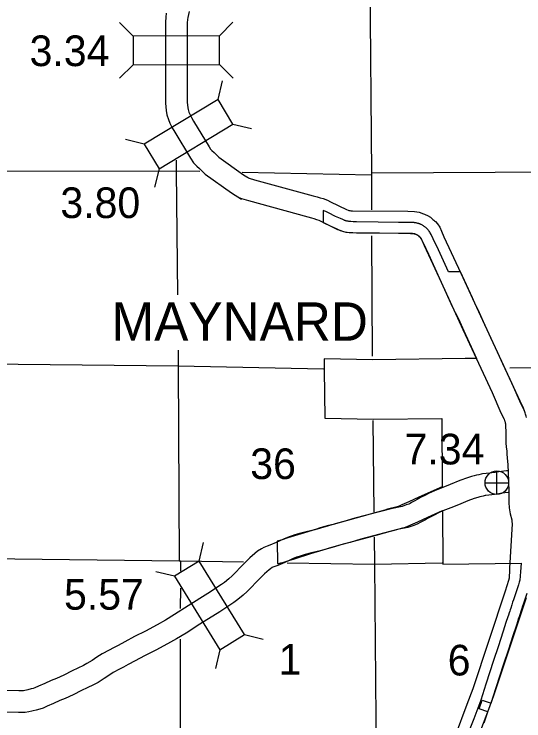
# Model space of a CAD drawing. Extents: x 1369885 to 1370219, y 379980 to 380218.
# Drawn here: x 1369916.19 to 1369938.61, y 380148.46 to 380179.57 of the extents above; entities that cross this region are included whole.
import ezdxf

# ---------------------------------------------------------------- set-up
doc = ezdxf.new("R2010")
doc.units = 0
for name, color, linetype in [('Level 10', 7, 'Continuous'), ('Level 20', 7, 'Continuous'), ('Level 25', 7, 'Continuous'), ('Level 26', 7, 'Continuous'), ('Level 4', 7, 'Continuous'), ('Level 5', 7, 'Continuous'), ('Level 58', 7, 'Continuous'), ('Level 6', 7, 'Continuous')]:
    doc.layers.add(name, color=color, linetype=linetype)

msp = doc.modelspace()

# ---------------------------------------------------------------- linework, layer by layer
at = {"layer": 'Level 10'}
for points in [[(1369923.887, 380179.675), (1369923.854, 380179.553), (1369923.824, 380179.422), (1369923.809, 380179.331), (1369923.799, 380179.18), (1369923.806, 380175.686), (1369923.826, 380175.447), (1369923.84, 380175.369), (1369923.88, 380175.25), (1369923.915, 380175.157), (1369923.989, 380175.017), (1369924.081, 380174.851), (1369924.762, 380173.726), (1369924.831, 380173.616), (1369924.882, 380173.564), (1369924.99, 380173.469), (1369925.14, 380173.322), (1369925.192, 380173.276), (1369926.282, 380172.499), (1369926.424, 380172.41), (1369926.449, 380172.386), (1369926.492, 380172.36)], [(1369922.883, 380179.605), (1369922.856, 380179.438), (1369922.841, 380179.21), (1369922.848, 380175.645), (1369922.875, 380175.322), (1369922.909, 380175.131), (1369922.977, 380174.927), (1369923.041, 380174.762), (1369923.146, 380174.562), (1369923.252, 380174.37), (1369923.946, 380173.223), (1369924.074, 380173.02), (1369924.222, 380172.868), (1369924.339, 380172.765), (1369924.486, 380172.622), (1369924.593, 380172.526), (1369925.747, 380171.704), (1369926.196, 380171.419)], [(1369926.438, 380172.388), (1369926.532, 380172.346), (1369926.759, 380172.276), (1369929.338, 380171.567), (1369929.523, 380171.523), (1369929.656, 380171.482), (1369929.78, 380171.445), (1369929.974, 380171.377), (1369930.105, 380171.308), (1369930.811, 380170.968), (1369930.879, 380170.94), (1369930.915, 380170.925), (1369930.955, 380170.916), (1369930.994, 380170.911), (1369931.066, 380170.911), (1369933.503, 380170.887), (1369933.803, 380170.873), (1369934.01, 380170.846), (1369934.189, 380170.782), (1369934.239, 380170.755), (1369934.263, 380170.745), (1369934.365, 380170.7), (1369934.498, 380170.629), (1369934.552, 380170.579), (1369934.611, 380170.533), (1369934.65, 380170.497), (1369934.681, 380170.468), (1369934.722, 380170.435), (1369934.812, 380170.336), (1369934.911, 380170.185), (1369934.992, 380170.02), (1369935.096, 380169.771), (1369935.836, 380168.168), (1369936.797, 380166.091), (1369938.088, 380163.302), (1369938.473, 380162.421), (1369938.607, 380162.151), (1369938.643, 380162.069)], [(1369926.049, 380171.512), (1369926.196, 380171.447), (1369926.492, 380171.356), (1369929.101, 380170.638), (1369929.27, 380170.598), (1369929.377, 380170.565), (1369929.485, 380170.533), (1369929.589, 380170.497), (1369929.673, 380170.452), (1369930.417, 380170.094), (1369930.518, 380170.052), (1369930.631, 380170.007), (1369930.784, 380169.972), (1369930.931, 380169.952), (1369931.064, 380169.953), (1369933.476, 380169.929), (1369933.719, 380169.918), (1369933.783, 380169.909), (1369933.798, 380169.904), (1369933.826, 380169.889), (1369933.886, 380169.864), (1369933.943, 380169.839), (1369933.989, 380169.803), (1369933.996, 380169.796), (1369934.051, 380169.745), (1369934.056, 380169.741), (1369934.076, 380169.71), (1369934.119, 380169.623), (1369934.218, 380169.385), (1369934.966, 380167.766), (1369935.928, 380165.688), (1369937.214, 380162.909), (1369937.604, 380162.016), (1369937.739, 380161.744), (1369937.745, 380161.732), (1369937.76, 380161.682), (1369937.78, 380161.644), (1369937.791, 380161.578), (1369937.799, 380161.532), (1369937.806, 380161.41), (1369937.814, 380161.196), (1369937.814, 380160.93), (1369937.824, 380160.683), (1369937.837, 380160.521), (1369937.857, 380160.328), (1369937.868, 380160.201), (1369937.88, 380160.031), (1369937.889, 380159.879), (1369937.9, 380159.745), (1369937.931, 380159.007), (1369937.942, 380158.54), (1369937.942, 380158.284), (1369937.95, 380158.066), (1369937.962, 380157.835), (1369938.007, 380157.576), (1369938.078, 380157.311), (1369938.086, 380157.23), (1369938.09, 380157.135), (1369937.979, 380155.177), (1369937.974, 380154.973), (1369937.966, 380154.88), (1369937.957, 380154.741), (1369937.928, 380154.638), (1369937.793, 380154.164), (1369936.366, 380149.875), (1369936.108, 380149.178), (1369935.591, 380147.802)], [(1369937.902, 380159.464), (1369937.84, 380159.459), (1369937.514, 380159.427), (1369937.342, 380159.395), (1369937.206, 380159.372), (1369937.116, 380159.367), (1369936.796, 380159.327), (1369936.726, 380159.315), (1369936.627, 380159.295), (1369936.526, 380159.274), (1369936.417, 380159.245), (1369936.312, 380159.215), (1369936.127, 380159.159), (1369935.799, 380159.04), (1369935.371, 380158.859), (1369935.042, 380158.727), (1369934.684, 380158.586), (1369934.449, 380158.485), (1369934.251, 380158.386), (1369934.068, 380158.289), (1369933.92, 380158.209), (1369933.809, 380158.148), (1369933.671, 380158.069), (1369933.603, 380158.031), (1369933.55, 380158.004), (1369933.44, 380157.963), (1369933.25, 380157.895), (1369932.838, 380157.811), (1369931.182, 380157.382), (1369930.698, 380157.235), (1369930.411, 380157.155), (1369930.02, 380157.046), (1369929.411, 380156.875), (1369929.038, 380156.784), (1369928.735, 380156.707), (1369928.531, 380156.644), (1369928.425, 380156.611), (1369928.284, 380156.563), (1369928.067, 380156.479), (1369927.88, 380156.384), (1369927.711, 380156.309), (1369927.435, 380156.191), (1369927.323, 380156.151), (1369927.179, 380156.095), (1369927.063, 380156.036), (1369926.891, 380155.924), (1369926.776, 380155.825), (1369926.56, 380155.632), (1369926.364, 380155.446), (1369926.125, 380155.21), (1369925.948, 380155.012), (1369925.776, 380154.849), (1369925.626, 380154.708), (1369925.446, 380154.557), (1369925.305, 380154.457), (1369924.711, 380154.059), (1369923.851, 380153.528), (1369923.24, 380153.137), (1369922.846, 380152.891), (1369922.481, 380152.691), (1369921.971, 380152.415), (1369921.484, 380152.169), (1369921.058, 380151.941), (1369920.759, 380151.782), (1369920.558, 380151.673), (1369920.374, 380151.579), (1369920.067, 380151.411), (1369919.83, 380151.262), (1369919.619, 380151.121), (1369919.394, 380150.978), (1369919.244, 380150.895), (1369918.985, 380150.773), (1369918.74, 380150.656), (1369918.372, 380150.478), (1369918.051, 380150.327), (1369917.82, 380150.232), (1369917.535, 380150.102), (1369917.258, 380149.981), (1369917.1, 380149.912), (1369917.032, 380149.886), (1369916.933, 380149.863), (1369916.797, 380149.829), (1369916.73, 380149.812), (1369916.657, 380149.793), (1369916.6, 380149.785), (1369916.389, 380149.781), (1369915.778, 380149.797)], [(1369937.928, 380158.505), (1369937.925, 380158.504), (1369937.647, 380158.477), (1369937.509, 380158.452), (1369937.316, 380158.418), (1369937.202, 380158.412), (1369936.938, 380158.379), (1369936.901, 380158.373), (1369936.817, 380158.356), (1369936.747, 380158.342), (1369936.673, 380158.322), (1369936.583, 380158.296), (1369936.43, 380158.249), (1369936.15, 380158.148), (1369935.736, 380157.973), (1369935.396, 380157.836), (1369935.048, 380157.699), (1369934.853, 380157.616), (1369934.69, 380157.534), (1369934.52, 380157.444), (1369934.377, 380157.366), (1369934.277, 380157.312), (1369934.142, 380157.235), (1369934.055, 380157.186), (1369933.94, 380157.127), (1369933.769, 380157.063), (1369933.508, 380156.97), (1369933.055, 380156.877), (1369931.442, 380156.459), (1369930.965, 380156.314), (1369930.667, 380156.232), (1369930.278, 380156.123), (1369929.654, 380155.948), (1369929.271, 380155.855), (1369928.995, 380155.784), (1369928.815, 380155.729), (1369928.721, 380155.699), (1369928.611, 380155.662), (1369928.459, 380155.603), (1369928.292, 380155.518), (1369928.093, 380155.43), (1369927.783, 380155.297), (1369927.657, 380155.253), (1369927.57, 380155.219), (1369927.543, 380155.205), (1369927.468, 380155.156), (1369927.407, 380155.104), (1369927.209, 380154.926), (1369927.03, 380154.757), (1369926.821, 380154.551), (1369926.637, 380154.344), (1369926.433, 380154.151), (1369926.262, 380153.991), (1369926.033, 380153.798), (1369925.849, 380153.668), (1369925.23, 380153.253), (1369924.361, 380152.717), (1369923.752, 380152.327), (1369923.331, 380152.064), (1369922.94, 380151.849), (1369922.415, 380151.565), (1369921.926, 380151.319), (1369921.509, 380151.096), (1369921.212, 380150.938), (1369921.005, 380150.825), (1369920.822, 380150.732), (1369920.552, 380150.584), (1369920.352, 380150.458), (1369920.144, 380150.319), (1369919.882, 380150.152), (1369919.679, 380150.041), (1369919.396, 380149.908), (1369919.156, 380149.792), (1369918.784, 380149.613), (1369918.439, 380149.45), (1369918.202, 380149.353), (1369917.926, 380149.226), (1369917.642, 380149.103), (1369917.463, 380149.025), (1369917.313, 380148.968), (1369917.159, 380148.932), (1369917.03, 380148.899), (1369916.965, 380148.883), (1369916.843, 380148.852), (1369916.678, 380148.828), (1369916.385, 380148.823), (1369915.761, 380148.839)], [(1369938.709, 380153.881), (1369937.27, 380149.557), (1369937.006, 380148.844), (1369936.488, 380147.464)]]:
    msp.add_lwpolyline(points, dxfattribs=at)
at = {"layer": 'Level 20'}
for p, q in [((1369921.424, 380178.603), (1369920.826, 380179.198)), ((1369925.219, 380178.61), (1369925.814, 380179.208)), ((1369921.426, 380177.338), (1369920.831, 380176.74)), ((1369925.221, 380177.345), (1369925.819, 380176.75)), ((1369925.157, 380175.812), (1369925.359, 380176.631)), ((1369925.812, 380174.73), (1369926.631, 380174.528)), ((1369921.911, 380173.847), (1369921.092, 380174.048)), ((1369922.566, 380172.764), (1369922.364, 380171.946)), ((1369924.322, 380155.486), (1369924.517, 380156.307)), ((1369923.246, 380154.822), (1369922.425, 380155.016)), ((1369926.316, 380152.257), (1369927.137, 380152.063)), ((1369925.24, 380151.592), (1369925.046, 380150.772))]:
    msp.add_line(p, q, dxfattribs=at)
for points in [[(1369921.426, 380177.338), (1369925.221, 380177.345), (1369925.219, 380178.61), (1369921.424, 380178.603)], [(1369922.566, 380172.764), (1369925.812, 380174.73), (1369925.157, 380175.812), (1369921.911, 380173.847)], [(1369923.246, 380154.822), (1369925.24, 380151.592), (1369926.316, 380152.257), (1369924.322, 380155.486)]]:
    msp.add_lwpolyline(points, close=True, dxfattribs=at)
at = {"layer": 'Level 26'}
for p, q in [((1369937.42, 380158.422), (1369937.42, 380159.46)), ((1369936.9, 380158.941), (1369937.939, 380158.941))]:
    msp.add_line(p, q, dxfattribs=at)
msp.add_circle((1369937.42, 380158.941), 0.519, dxfattribs=at)
at = {"layer": 'Level 4'}
for points in [[(1369931.814, 380184.515), (1369931.837, 380181.126), (1369931.833, 380181.027), (1369931.902, 380172.561), (1369931.901, 380172.481), (1369931.907, 380170.949)], [(1369931.911, 380169.81), (1369931.932, 380164.509)], [(1369931.961, 380161.681), (1369932.01, 380157.643)], [(1369932.023, 380156.54), (1369932.037, 380155.354), (1369932.115, 380146.851), (1369932.126, 380146.707), (1369932.199, 380139.989)], [(1369926.278, 380155.441), (1369923.502, 380155.488), (1369923.441, 380155.484), (1369914.997, 380155.591), (1369914.93, 380155.597), (1369906.42, 380155.85), (1369906.378, 380155.851), (1369902.311, 380155.872)], [(1369935.013, 380155.396), (1369932.047, 380155.348), (1369928.199, 380155.408)]]:
    msp.add_lwpolyline(points, dxfattribs=at)
at = {"layer": 'Level 5'}
for points in [[(1369923.321, 380173.142), (1369923.318, 380172.66), (1369923.375, 380167.204)], [(1369924.364, 380172.638), (1369923.318, 380172.66), (1369914.846, 380172.646), (1369906.147, 380173.018), (1369902.311, 380173.036)], [(1369948.675, 380172.819), (1369940.069, 380172.615), (1369931.902, 380172.561)], [(1369931.901, 380172.481), (1369926.215, 380172.6)], [(1369923.4, 380164.783), (1369923.407, 380164.071), (1369923.441, 380155.484)], [(1369929.799, 380163.946), (1369923.407, 380164.071), (1369914.944, 380164.166), (1369906.209, 380164.33), (1369902.311, 380164.411)], [(1369944.671, 380164.098), (1369940.216, 380164.013), (1369938, 380163.984)], [(1369923.502, 380155.488), (1369923.501, 380155.046)], [(1369923.5, 380154.299), (1369923.498, 380153.409)], [(1369923.496, 380152.058), (1369923.487, 380146.925), (1369923.615, 380138.382)]]:
    msp.add_lwpolyline(points, dxfattribs=at)
at = {"layer": 'Level 6'}
for points in [[(1369935.295, 380168.222), (1369934.849, 380169.198), (1369934.623, 380169.682), (1369934.531, 380169.871), (1369934.489, 380169.942), (1369934.468, 380169.976), (1369934.446, 380170.008), (1369934.42, 380170.044), (1369934.401, 380170.07), (1369934.372, 380170.105), (1369934.349, 380170.128), (1369934.319, 380170.156), (1369934.299, 380170.173), (1369934.272, 380170.194), (1369934.25, 380170.209), (1369934.228, 380170.224), (1369934.193, 380170.247), (1369934.171, 380170.261), (1369934.149, 380170.273), (1369934.123, 380170.287), (1369934.095, 380170.302), (1369934.08, 380170.308), (1369934.065, 380170.315), (1369934.048, 380170.322), (1369934.031, 380170.329), (1369934.01, 380170.336), (1369933.988, 380170.344), (1369933.968, 380170.35), (1369933.944, 380170.357), (1369933.921, 380170.363), (1369933.897, 380170.37), (1369933.873, 380170.376), (1369933.847, 380170.38), (1369933.82, 380170.384), (1369933.803, 380170.386), (1369933.783, 380170.388), (1369933.719, 380170.393), (1369933.437, 380170.4), (1369933.094, 380170.402), (1369932.202, 380170.413), (1369931.254, 380170.426), (1369931.107, 380170.43), (1369930.996, 380170.436), (1369930.904, 380170.445), (1369930.875, 380170.45), (1369930.851, 380170.455), (1369930.826, 380170.46), (1369930.796, 380170.468), (1369930.771, 380170.475), (1369930.745, 380170.483), (1369930.725, 380170.49), (1369930.7, 380170.499), (1369930.646, 380170.52), (1369930.542, 380170.564), (1369930.328, 380170.666), (1369930.011, 380170.822), (1369929.934, 380170.858), (1369929.897, 380170.875), (1369929.856, 380170.892), (1369929.779, 380170.922), (1369929.782, 380170.401)], [(1369929.782, 380170.401), (1369930.119, 380170.234), (1369930.347, 380170.126), (1369930.467, 380170.076), (1369930.536, 380170.049), (1369930.595, 380170.028), (1369930.672, 380170.005), (1369930.752, 380169.985), (1369930.837, 380169.97), (1369930.959, 380169.958), (1369931.088, 380169.951), (1369931.244, 380169.947), (1369932.196, 380169.934), (1369933.09, 380169.923), (1369933.429, 380169.921), (1369933.628, 380169.916), (1369933.717, 380169.91), (1369933.757, 380169.904), (1369933.783, 380169.901), (1369933.802, 380169.897), (1369933.827, 380169.89), (1369933.843, 380169.886), (1369933.865, 380169.878), (1369933.879, 380169.873), (1369933.902, 380169.862), (1369933.918, 380169.853), (1369933.942, 380169.839), (1369933.961, 380169.827), (1369933.988, 380169.808), (1369933.999, 380169.799), (1369934.027, 380169.769), (1369934.052, 380169.735), (1369934.079, 380169.694), (1369934.108, 380169.645), (1369934.19, 380169.476), (1369934.414, 380168.997), (1369934.904, 380167.925), (1369935.477, 380166.674), (1369935.589, 380166.43), (1369935.729, 380166.148), (1369935.963, 380165.625), (1369936.289, 380164.916), (1369936.522, 380164.409)], [(1369938.725, 380161.817), (1369938.713, 380161.873), (1369938.689, 380161.96), (1369938.67, 380162.024), (1369938.639, 380162.104), (1369938.59, 380162.219), (1369938.447, 380162.528), (1369938.075, 380163.318), (1369937.688, 380164.174), (1369937.46, 380164.662), (1369937.16, 380165.316), (1369936.836, 380166.021), (1369936.596, 380166.557), (1369936.454, 380166.843), (1369936.348, 380167.074), (1369935.82, 380168.227), (1369935.295, 380168.222)], [(1369936.522, 380164.409), (1369936.022, 380164.403), (1369931.963, 380164.357), (1369929.823, 380164.396), (1369929.827, 380163.917), (1369929.851, 380161.777), (1369931.993, 380161.741), (1369934.995, 380161.775), (1369935.022, 380158.754)], [(1369935.022, 380158.754), (1369933.997, 380158.299), (1369933.557, 380158.103), (1369933.244, 380157.963), (1369933.13, 380157.911), (1369933.037, 380157.883), (1369932.611, 380157.771), (1369932.488, 380157.737), (1369931.848, 380157.559), (1369930.22, 380157.11), (1369930.01, 380157.052), (1369929.8, 380156.994), (1369929.601, 380156.937), (1369929.49, 380156.901), (1369928.956, 380156.735), (1369928.232, 380156.51), (1369927.984, 380156.434), (1369927.765, 380156.367)], [(1369927.838, 380155.384), (1369927.916, 380155.409), (1369928.047, 380155.451), (1369928.266, 380155.518), (1369928.515, 380155.595), (1369929.241, 380155.82), (1369929.779, 380155.988), (1369929.88, 380156.02), (1369930.06, 380156.072), (1369930.264, 380156.128), (1369930.473, 380156.186), (1369931.956, 380156.592), (1369932.112, 380156.638), (1369932.743, 380156.814), (1369932.859, 380156.845), (1369933.287, 380156.958), (1369933.354, 380156.976), (1369933.436, 380157.002), (1369933.509, 380157.03), (1369933.632, 380157.088), (1369933.946, 380157.227), (1369934.388, 380157.424), (1369935.031, 380157.712)], [(1369935.031, 380157.712), (1369935.052, 380155.363), (1369938.495, 380155.401), (1369938.468, 380155.025), (1369938.451, 380154.838), (1369938.443, 380154.769), (1369938.436, 380154.71), (1369938.428, 380154.655), (1369938.42, 380154.616), (1369938.409, 380154.57), (1369938.392, 380154.506), (1369938.375, 380154.449), (1369938.301, 380154.228), (1369938.15, 380153.792), (1369938.114, 380153.68), (1369938.079, 380153.561), (1369938.039, 380153.424), (1369938.015, 380153.353), (1369937.995, 380153.288), (1369937.97, 380153.215), (1369937.93, 380153.109), (1369937.905, 380153.036), (1369937.824, 380152.789), (1369937.697, 380152.412), (1369937.481, 380151.725), (1369937.271, 380151.115), (1369936.941, 380150.08), (1369936.712, 380149.377), (1369936.411, 380148.55), (1369936.093, 380147.74)], [(1369927.765, 380156.367), (1369927.775, 380155.385), (1369927.838, 380155.384)], [(1369936.859, 380148.38), (1369937.031, 380148.852), (1369936.645, 380148.992), (1369936.774, 380149.364), (1369937.17, 380149.235), (1369937.397, 380149.933), (1369937.726, 380150.964), (1369937.936, 380151.575), (1369938.152, 380152.263), (1369938.279, 380152.638), (1369938.36, 380152.884), (1369938.381, 380152.947), (1369938.421, 380153.052), (1369938.451, 380153.14), (1369938.496, 380153.282), (1369938.538, 380153.424), (1369938.572, 380153.539), (1369938.579, 380153.559), (1369938.755, 380154.074)]]:
    msp.add_lwpolyline(points, dxfattribs=at)

# ---------------------------------------------------------------- texts
at = {"layer": 'Level 25'}
msp.add_text('7.34', height=1.3493, dxfattribs=at).set_placement((1369933.363, 380159.747))
at = {"layer": 'Level 5'}
for s, height, p in [('MAYNARD', 1.6867, (1369920.471, 380165.193)), ('36', 1.3493, (1369926.575, 380159.103)), ('1', 1.349, (1369927.825, 380150.494)), ('6', 1.349, (1369935.26, 380150.458))]:
    msp.add_text(s, height=height, dxfattribs=at).set_placement(p)
at = {"layer": 'Level 58'}
for s, p in [('3.34', (1369916.869, 380177.278)), ('3.80', (1369918.224, 380170.59)), ('5.57', (1369918.384, 380153.354))]:
    msp.add_text(s, height=1.3493, dxfattribs=at).set_placement(p)

doc.saveas('drawing.dxf')
